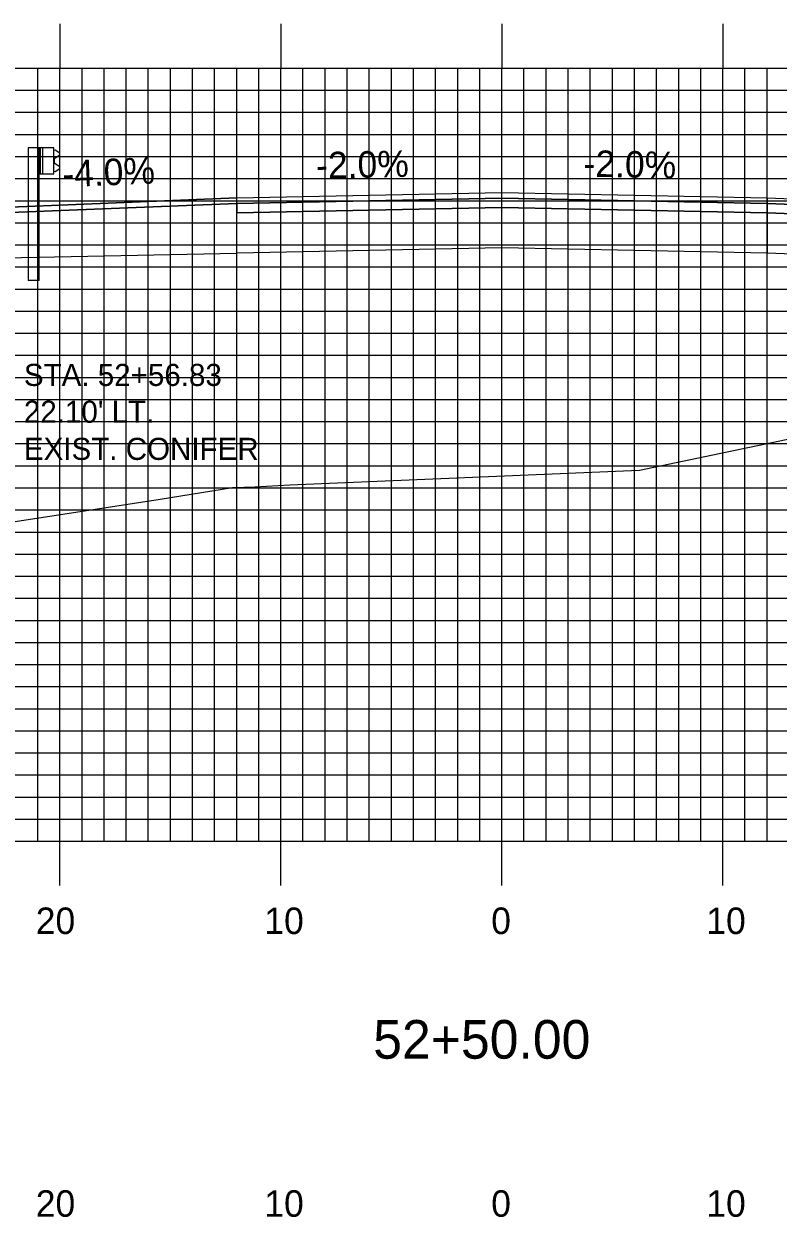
# Model space of a CAD drawing. Extents: x 1755888 to 1756232, y 442591 to 442811.
# Drawn here: x 1756032.4 to 1756066.6, y 442651.6 to 442705.7 of the extents above; entities that cross this region are included whole.
import ezdxf

# ---------------------------------------------------------------- set-up
doc = ezdxf.new("R2010")
doc.units = 0
for name, color, linetype in [('ANNOTATION', 7, 'Continuous'), ('D_Guardrail_Beam_Lt', 7, 'Continuous'), ('D_Roadway_Centerline', 7, 'Continuous'), ('D_Roadway_Edge_Shoulder', 7, 'Continuous'), ('D_Roadway_Edge_TW', 7, 'Continuous'), ('D_Roadway_Pavement', 7, 'Continuous'), ('D_Roadway_SubGrade', 7, 'Continuous'), ('D_Text_Monospaced', 7, 'Continuous'), ('H_V ANNOTATION', 7, 'Continuous'), ('MAJOR', 7, 'Continuous'), ('MINOR', 7, 'Continuous'), ('S_Roadway_Centerline', 7, 'Continuous')]:
    doc.layers.add(name, color=color, linetype=linetype)

msp = doc.modelspace()

# ---------------------------------------------------------------- linework, layer by layer
at = {"layer": 'D_Guardrail_Beam_Lt'}
for p, q in [((1756032.628, 442700.051), (1756032.628, 442694.051)), ((1756033.098, 442700.051), (1756032.628, 442700.051)), ((1756033.786, 442700.051), (1756033.098, 442700.051)), ((1756033.098, 442700.051), (1756033.098, 442698.885)), ((1756033.161, 442700.051), (1756033.161, 442698.885)), ((1756033.265, 442700.051), (1756033.265, 442698.885)), ((1756033.786, 442698.885), (1756033.786, 442700.051)), ((1756033.786, 442699.968), (1756033.86, 442699.953)), ((1756034.019, 442699.704), (1756033.824, 442699.567)), ((1756033.876, 442699.947), (1756034.019, 442699.847)), ((1756033.79, 442699.503), (1756033.79, 442699.433)), ((1756033.824, 442699.368), (1756034.019, 442699.232)), ((1756033.098, 442698.885), (1756033.786, 442698.885)), ((1756033.119, 442694.051), (1756033.119, 442698.885)), ((1756033.86, 442698.982), (1756033.786, 442698.968)), ((1756034.019, 442699.089), (1756033.876, 442698.989)), ((1756033.119, 442694.051), (1756032.628, 442694.051))]:
    msp.add_line(p, q, dxfattribs=at)
for centre, major_axis, start_param, end_param in [((1756033.852, 442699.913), (0.0417, 0), 0.959931, 1.376053), ((1756033.969, 442699.775), (0.0877, 0), 5.323254, 7.243116), ((1756033.869, 442699.503), (-0.0789, 0), 5.323254, 6.283185), ((1756033.869, 442699.433), (-0.0789, 0), 6.283185, 7.243116), ((1756033.969, 442699.161), (0.0877, 0), 5.323254, 7.243116), ((1756033.852, 442699.023), (0.0417, 0), 4.907132, 5.323254)]:
    msp.add_ellipse(centre, major_axis=major_axis, ratio=0.995501, start_param=start_param, end_param=end_param, dxfattribs=at)
at = {"layer": 'D_Roadway_Centerline'}
msp.add_lwpolyline([(1755988.922, 442676.281), (1756026.307, 442694.973), (1756031.057, 442697.348), (1756034.057, 442697.468), (1756042.057, 442697.788), (1756054.057, 442698.028), (1756066.057, 442697.788), (1756078.057, 442697.314), (1756093.723, 442696.688), (1756103.154, 442694.068), (1756119.307, 442689.581)], dxfattribs=at)
at = {"layer": 'D_Roadway_Edge_Shoulder'}
msp.add_lwpolyline([(1756042.057, 442697.788), (1756034.057, 442697.468), (1756034.057, 442697.468), (1756031.057, 442697.348), (1756031.057, 442697.098), (1756042.057, 442697.538)], close=True, dxfattribs=at)
at = {"layer": 'D_Roadway_Edge_TW'}
for points in [[(1756042.057, 442697.538), (1756042.057, 442697.788), (1756054.057, 442698.028), (1756066.057, 442697.788), (1756066.057, 442697.538), (1756054.057, 442697.778)], [(1756066.057, 442697.788), (1756078.057, 442697.314), (1756078.057, 442697.064), (1756066.057, 442697.538)]]:
    msp.add_lwpolyline(points, close=True, dxfattribs=at)
at = {"layer": 'D_Roadway_Pavement'}
for points in [[(1756042.057, 442697.121), (1756042.057, 442697.538), (1756054.057, 442697.778), (1756066.057, 442697.538), (1756066.057, 442697.121), (1756054.057, 442697.361)], [(1756066.057, 442697.538), (1756078.057, 442697.064), (1756078.057, 442696.648), (1756066.057, 442697.121)]]:
    msp.add_lwpolyline(points, close=True, dxfattribs=at)
msp.add_lwpolyline([(1756042.057, 442697.538), (1756042.057, 442697.121)], dxfattribs=at)
at = {"layer": 'D_Roadway_SubGrade'}
for points in [[(1756042.057, 442697.121), (1756042.057, 442697.538), (1756031.057, 442697.098), (1756031.057, 442697.348), (1756026.307, 442694.973), (1756042.057, 442695.288)], [(1756042.057, 442695.288), (1756042.057, 442697.121), (1756054.057, 442697.361), (1756066.057, 442697.121), (1756066.057, 442695.288), (1756054.057, 442695.528)], [(1756066.057, 442697.121), (1756078.057, 442696.648), (1756078.057, 442694.814), (1756066.057, 442695.288)]]:
    msp.add_lwpolyline(points, close=True, dxfattribs=at)
at = {"layer": 'MAJOR'}
for p, q in [((1756034.057, 442705.669), (1756034.057, 442703.665)), ((1756044.057, 442705.669), (1756044.057, 442703.665)), ((1756054.057, 442705.669), (1756054.057, 442703.665)), ((1756064.057, 442705.669), (1756064.057, 442703.665)), ((1755914.057, 442703.665), (1756194.057, 442703.665)), ((1755914.057, 442703.665), (1756194.057, 442703.665)), ((1756034.057, 442668.665), (1756034.057, 442703.665)), ((1756044.057, 442668.665), (1756044.057, 442703.665)), ((1756054.057, 442668.665), (1756054.057, 442703.665)), ((1756064.057, 442668.665), (1756064.057, 442703.665)), ((1755914.057, 442698.665), (1756194.057, 442698.665)), ((1755914.057, 442693.665), (1756194.057, 442693.665)), ((1755914.057, 442688.665), (1756194.057, 442688.665)), ((1755914.057, 442683.665), (1756194.057, 442683.665)), ((1755914.057, 442678.665), (1756194.057, 442678.665)), ((1755914.057, 442673.665), (1756194.057, 442673.665)), ((1755914.057, 442668.665), (1756194.057, 442668.665)), ((1755914.057, 442668.665), (1756194.057, 442668.665)), ((1756034.057, 442666.661), (1756034.057, 442668.665)), ((1756044.057, 442666.661), (1756044.057, 442668.665)), ((1756054.057, 442666.661), (1756054.057, 442668.665)), ((1756064.057, 442666.661), (1756064.057, 442668.665))]:
    msp.add_line(p, q, dxfattribs=at)
at = {"layer": 'MINOR'}
for p, q in [((1756033.057, 442668.665), (1756033.057, 442703.665)), ((1756035.057, 442668.665), (1756035.057, 442703.665)), ((1756036.057, 442668.665), (1756036.057, 442703.665)), ((1756037.057, 442668.665), (1756037.057, 442703.665)), ((1756038.057, 442668.665), (1756038.057, 442703.665)), ((1756039.057, 442668.665), (1756039.057, 442703.665)), ((1756040.057, 442668.665), (1756040.057, 442703.665)), ((1756041.057, 442668.665), (1756041.057, 442703.665)), ((1756042.057, 442668.665), (1756042.057, 442703.665)), ((1756043.057, 442668.665), (1756043.057, 442703.665)), ((1756045.057, 442668.665), (1756045.057, 442703.665)), ((1756046.057, 442668.665), (1756046.057, 442703.665)), ((1756047.057, 442668.665), (1756047.057, 442703.665)), ((1756048.057, 442668.665), (1756048.057, 442703.665)), ((1756049.057, 442668.665), (1756049.057, 442703.665)), ((1756050.057, 442668.665), (1756050.057, 442703.665)), ((1756051.057, 442668.665), (1756051.057, 442703.665)), ((1756052.057, 442668.665), (1756052.057, 442703.665)), ((1756053.057, 442668.665), (1756053.057, 442703.665)), ((1756055.057, 442668.665), (1756055.057, 442703.665)), ((1756056.057, 442668.665), (1756056.057, 442703.665)), ((1756057.057, 442668.665), (1756057.057, 442703.665)), ((1756058.057, 442668.665), (1756058.057, 442703.665)), ((1756059.057, 442668.665), (1756059.057, 442703.665)), ((1756060.057, 442668.665), (1756060.057, 442703.665)), ((1756061.057, 442668.665), (1756061.057, 442703.665)), ((1756062.057, 442668.665), (1756062.057, 442703.665)), ((1756063.057, 442668.665), (1756063.057, 442703.665)), ((1756065.057, 442668.665), (1756065.057, 442703.665)), ((1756066.057, 442668.665), (1756066.057, 442703.665)), ((1755914.057, 442702.665), (1756194.057, 442702.665)), ((1755914.057, 442701.665), (1756194.057, 442701.665)), ((1755914.057, 442700.665), (1756194.057, 442700.665)), ((1755914.057, 442699.665), (1756194.057, 442699.665)), ((1755914.057, 442697.665), (1756194.057, 442697.665)), ((1755914.057, 442696.665), (1756194.057, 442696.665)), ((1755914.057, 442695.665), (1756194.057, 442695.665)), ((1755914.057, 442694.665), (1756194.057, 442694.665)), ((1755914.057, 442692.665), (1756194.057, 442692.665)), ((1755914.057, 442691.665), (1756194.057, 442691.665)), ((1755914.057, 442690.665), (1756194.057, 442690.665)), ((1755914.057, 442689.665), (1756194.057, 442689.665)), ((1755914.057, 442687.665), (1756194.057, 442687.665)), ((1755914.057, 442686.665), (1756194.057, 442686.665)), ((1755914.057, 442685.665), (1756194.057, 442685.665)), ((1755914.057, 442684.665), (1756194.057, 442684.665)), ((1755914.057, 442682.665), (1756194.057, 442682.665)), ((1755914.057, 442681.665), (1756194.057, 442681.665)), ((1755914.057, 442680.665), (1756194.057, 442680.665)), ((1755914.057, 442679.665), (1756194.057, 442679.665)), ((1755914.057, 442677.665), (1756194.057, 442677.665)), ((1755914.057, 442676.665), (1756194.057, 442676.665)), ((1755914.057, 442675.665), (1756194.057, 442675.665)), ((1755914.057, 442674.665), (1756194.057, 442674.665)), ((1755914.057, 442672.665), (1756194.057, 442672.665)), ((1755914.057, 442671.665), (1756194.057, 442671.665)), ((1755914.057, 442670.665), (1756194.057, 442670.665)), ((1755914.057, 442669.665), (1756194.057, 442669.665))]:
    msp.add_line(p, q, dxfattribs=at)
at = {"layer": 'S_Roadway_Centerline'}
msp.add_lwpolyline([(1756011.415, 442679.926), (1756013.978, 442680.371), (1756038.592, 442684.155), (1756041.872, 442684.674), (1756042.879, 442684.708), (1756044.461, 442684.799), (1756060.284, 442685.471), (1756075.572, 442688.669), (1756079.705, 442689.201), (1756081.969, 442689.651), (1756090.362, 442690.015), (1756099.67, 442689.942), (1756106.379, 442690.09), (1756121.311, 442689.502), (1756138.054, 442689.488), (1756139.019, 442689.391), (1756142.385, 442688.795), (1756158.924, 442685.483), (1756163.121, 442684.674), (1756170.029, 442683.558), (1756174.253, 442682.817), (1756177.852, 442682.58), (1756191.592, 442681.484), (1756194.057, 442681.352)], dxfattribs=at)

# ---------------------------------------------------------------- texts
at = {"layer": 'ANNOTATION'}
for s, rotation, p in [('-2.0%', 1.1458, (1756045.663, 442698.66)), ('-2.0%', 358.8542, (1756057.743, 442698.755)), ('-4.0%', 2.2906, (1756034.189, 442698.275))]:
    msp.add_text(s, height=1.2, rotation=rotation, dxfattribs=at).set_placement(p)
at = {"layer": 'D_Roadway_Centerline'}
for s, p in [('C', (1756054.052, 442698.028)), ('L', (1756054.057, 442698.021))]:
    msp.add_text(s, height=0.0146, dxfattribs=at).set_placement(p)
at = {"layer": 'D_Text_Monospaced'}
for s, height, p in [('STA. 52+56.83', 0.99996, (1756032.427, 442689.277)), ("22.10' LT.", 1, (1756032.427, 442687.609)), ('EXIST. CONIFER', 0.99996, (1756032.427, 442685.929))]:
    msp.add_text(s, height=height, dxfattribs=at).set_placement(p)
at = {"layer": 'H_V ANNOTATION'}
for s, height, p in [('20', 1.2, (1756032.965, 442664.465)), ('10', 1.2, (1756043.307, 442664.465)), ('0', 1.2, (1756053.575, 442664.465)), ('10', 1.2, (1756063.307, 442664.465)), ('52+50.00', 1.75, (1756048.235, 442658.821)), ('20', 1.2, (1756032.965, 442651.665)), ('10', 1.2, (1756043.307, 442651.665)), ('0', 1.2, (1756053.575, 442651.665)), ('10', 1.2, (1756063.307, 442651.665))]:
    msp.add_text(s, height=height, dxfattribs=at).set_placement(p)

doc.saveas('drawing.dxf')
